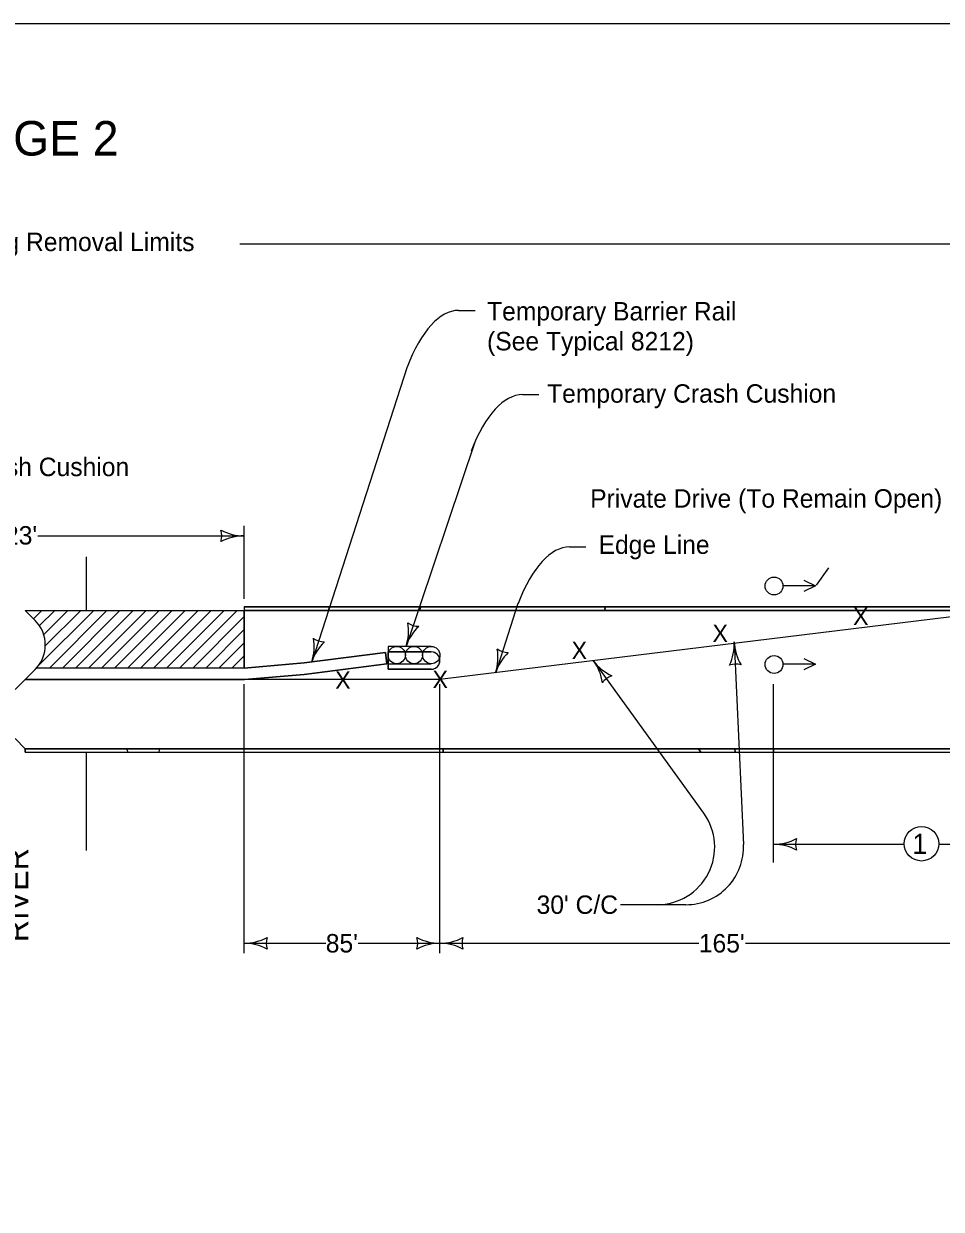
# Model space of a CAD drawing. Extents: x -2134934 to -2122394, y -2140205 to -2137036.
# Drawn here: x -2133366 to -2132569, y -2138065 to -2137036 of the extents above; entities that cross this region are included whole.
import ezdxf

# ---------------------------------------------------------------- set-up
doc = ezdxf.new("R2010")
doc.units = 0
for name, color, linetype in [('Barrier', 7, 'Continuous'), ('BridgeSuperStructureExisting', 7, 'Continuous'), ('Default', 7, 'Continuous'), ('dsnCellsNorthArrow', 7, 'Continuous'), ('DsnShtInsideBorder', 7, 'Continuous'), ('DsnShtPlotIdentification', 7, 'Continuous'), ('DsnShtPlotShape', 7, 'Continuous')]:
    doc.layers.add(name, color=color, linetype=linetype)

msp = doc.modelspace()

# ---------------------------------------------------------------- linework, layer by layer
at = {"layer": 'BridgeSuperStructureExisting'}
for p, q in [((-2133178, -2137227), (-2132514.4, -2137227)), ((-2132988.2, -2137284.8), (-2132973.9, -2137284.8)), ((-2133032.9, -2137333.9), (-2133115.7, -2137590)), ((-2132932.7, -2137357.9), (-2132918.5, -2137357.9)), ((-2132973.7, -2137398.2), (-2133033.8, -2137576.5)), ((-2133174.4, -2137535.2), (-2133174.4, -2137471.9)), ((-2133353.3, -2137480.5), (-2133174.4, -2137480.5)), ((-2133311.5, -2137498.8), (-2133311.5, -2137545.2)), ((-2132891.9, -2137490.1), (-2132877.7, -2137490.1)), ((-2132677.6, -2137523.2), (-2132666.8, -2137508.1)), ((-2132706.7, -2137523.7), (-2132678.8, -2137523.7)), ((-2132936.7, -2137539.2), (-2132956, -2137599.2)), ((-2133355.7, -2137553.9), (-2133364.4, -2137545.2)), ((-2133357.2, -2137552.4), (-2133350, -2137545.2)), ((-2133353.3, -2137593.7), (-2133304.8, -2137545.2)), ((-2133352, -2137558.4), (-2133338.7, -2137545.2)), ((-2133348.3, -2137566.1), (-2133327.4, -2137545.2)), ((-2133346.9, -2137576), (-2133316.1, -2137545.2)), ((-2133343.4, -2137595.2), (-2133293.4, -2137545.2)), ((-2133332.1, -2137595.2), (-2133282.1, -2137545.2)), ((-2133320.8, -2137595.2), (-2133270.8, -2137545.2)), ((-2133309.5, -2137595.2), (-2133259.5, -2137545.2)), ((-2133298.2, -2137595.2), (-2133248.2, -2137545.2)), ((-2133286.9, -2137595.2), (-2133236.9, -2137545.2)), ((-2133275.6, -2137595.2), (-2133225.6, -2137545.2)), ((-2133264.2, -2137595.2), (-2133214.2, -2137545.2)), ((-2133252.9, -2137595.2), (-2133202.9, -2137545.2)), ((-2133241.6, -2137595.2), (-2133191.6, -2137545.2)), ((-2133230.3, -2137595.2), (-2133180.3, -2137545.2)), ((-2133219, -2137595.2), (-2133174.4, -2137550.6)), ((-2133174.4, -2137595.2), (-2133174.4, -2137545.2)), ((-2131862, -2137545.2), (-2133174.4, -2137545.2)), ((-2133174.4, -2137545.2), (-2133174.4, -2137595.2)), ((-2132514.4, -2137545.2), (-2133004.4, -2137605.2)), ((-2133207.7, -2137595.2), (-2133174.4, -2137561.9)), ((-2133196.4, -2137595.2), (-2133174.4, -2137573.2)), ((-2133049.4, -2137576.5), (-2133049.4, -2137591.5)), ((-2133011.9, -2137576.5), (-2133049.4, -2137576.5)), ((-2133049.4, -2137596.2), (-2133049.4, -2137581.2)), ((-2133049.4, -2137581.2), (-2133011.9, -2137581.2)), ((-2132749, -2137572.6), (-2132740.9, -2137748.3)), ((-2133185.1, -2137595.2), (-2133174.4, -2137584.5)), ((-2133174.4, -2137595.2), (-2133122.2, -2137590.8)), ((-2133122.2, -2137590.8), (-2133174.3, -2137595.2)), ((-2133174.3, -2137595.2), (-2133122.2, -2137590.8)), ((-2133122.3, -2137600.8), (-2133050.4, -2137591.5)), ((-2133050.4, -2137591.5), (-2133122.3, -2137600.8)), ((-2133050.4, -2137591.5), (-2133122.3, -2137600.8)), ((-2133051.7, -2137581.6), (-2133122.2, -2137590.8)), ((-2133122.2, -2137590.8), (-2133051.7, -2137581.6)), ((-2133122.2, -2137590.8), (-2133051.7, -2137581.6)), ((-2133050.4, -2137591.5), (-2133051.7, -2137581.6)), ((-2133051.7, -2137581.6), (-2133050.4, -2137591.5)), ((-2133051.7, -2137581.6), (-2133050.4, -2137591.5)), ((-2133049.4, -2137591.5), (-2133011.9, -2137591.5)), ((-2132775.4, -2137721.3), (-2132871.2, -2137588.8)), ((-2132706.7, -2137591.7), (-2132678.8, -2137591.7)), ((-2133373.2, -2137613.9), (-2133355.7, -2137596.4)), ((-2133355.7, -2137596.4), (-2133364.4, -2137605.2)), ((-2133174.3, -2137595.2), (-2133354.4, -2137595.2)), ((-2133174.3, -2137595.2), (-2133354.4, -2137595.2)), ((-2133173.9, -2137605.2), (-2133122.3, -2137600.8)), ((-2133122.3, -2137600.8), (-2133173.9, -2137605.2)), ((-2133122.3, -2137600.8), (-2133173.9, -2137605.2)), ((-2133011.9, -2137596.2), (-2133049.4, -2137596.2)), ((-2133364.4, -2137605.2), (-2133173.9, -2137605.2)), ((-2133173.9, -2137605.2), (-2133364.4, -2137605.2)), ((-2133173.9, -2137605.2), (-2133364.4, -2137605.2)), ((-2133174.4, -2137842.8), (-2133174.4, -2137609.3)), ((-2133004.4, -2137605.2), (-2133173.9, -2137605.2)), ((-2133004.4, -2137842.8), (-2133004.4, -2137609.3)), ((-2132714.9, -2137764.1), (-2132714.9, -2137609.3)), ((-2133364.4, -2137665.2), (-2133373.2, -2137656.4)), ((-2133373.2, -2137656.4), (-2133364.4, -2137665.2)), ((-2133364.4, -2137665.2), (-2131862, -2137665.2)), ((-2133311.5, -2137668.2), (-2133311.5, -2137753.6)), ((-2132714.9, -2137748.2), (-2132601.4, -2137748.2)), ((-2132571.4, -2137748.2), (-2132514.9, -2137748.2)), ((-2132790.9, -2137800.6), (-2132847.6, -2137800.6)), ((-2133174.4, -2137834.1), (-2133103.5, -2137834.1)), ((-2133075.4, -2137834.1), (-2133004.4, -2137834.1)), ((-2133004.4, -2137834.1), (-2132779.7, -2137834.1)), ((-2132739.2, -2137834.1), (-2132514.4, -2137834.1))]:
    msp.add_line(p, q, dxfattribs=at)
for points in [[(-2132688.4, -2137518.9), (-2132678.4, -2137523.9), (-2132688.4, -2137528.9)], [(-2133364.4, -2137545.2), (-2133174.4, -2137545.2)], [(-2132688.4, -2137586.9), (-2132678.4, -2137591.9), (-2132688.4, -2137596.9)], [(-2133354.4, -2137595.2), (-2133354.5, -2137595.1)], [(-2133364.4, -2137605.2), (-2133364.4, -2137605.2), (-2133373.2, -2137613.9)]]:
    msp.add_lwpolyline(points, dxfattribs=at)
for centre, radius in [((-2132714.4, -2137524), 7.74), ((-2133041.9, -2137584), 7.5), ((-2133041.9, -2137584), 7.5), ((-2133026.9, -2137584), 7.5), ((-2133026.9, -2137584), 7.5), ((-2133011.9, -2137584), 7.5), ((-2133011.9, -2137584), 7.5), ((-2132714.4, -2137592.1), 7.74), ((-2132586.4, -2137747.7), 15)]:
    msp.add_circle(centre, radius, dxfattribs=at)
for centre, radius, start, end in [((-2133210.1, -2137480.5), 16.4, 342.2666, 17.7333), ((-2133174.4, -2137438), 42.5, 241.9275, 270), ((-2133174.4, -2137523), 42.5, 90, 118.0725), ((-2133376.9, -2137575.2), 30, 315, 45), ((-2133011.9, -2137588.7), 7.5, 269.9996, 90), ((-2133376.9, -2137575.2), 30, 315, 318.2713), ((-2132815.9, -2137750.6), 50, 270, 35.862), ((-2132714.9, -2137705.7), 42.5, 270, 298.0725), ((-2132679.3, -2137748.2), 16.4, 162.2666, 197.7334), ((-2132790.9, -2137750.6), 50, 270, 2.6154), ((-2132714.9, -2137790.7), 42.5, 61.9275, 90)]:
    msp.add_arc(centre, radius, start, end, dxfattribs=at)
for centre in [(-2132988.2, -2137497.7), (-2132932.7, -2137570.8), (-2132891.9, -2137703)]:
    msp.add_ellipse(centre, major_axis=(0, 212.9), ratio=0.328743, start_param=0, end_param=0.693162, dxfattribs=at)
at = {"layer": 'Default'}
msp.add_lwpolyline([(-2134934.4, -2137035.9), (-2131799.4, -2137035.9), (-2131799.4, -2139045.9), (-2134934.4, -2139045.9)], close=True, dxfattribs=at)
at = {"layer": 'DsnShtInsideBorder'}
for p, q in [((-2133011.9, -2137581.2), (-2133049.4, -2137581.2)), ((-2133049.4, -2137581.2), (-2133049.4, -2137596.2)), ((-2133049.4, -2137596.2), (-2133011.9, -2137596.2))]:
    msp.add_line(p, q, dxfattribs=at)
msp.add_arc((-2133011.9, -2137588.7), 7.5, 270.0024, 89.9972, dxfattribs=at)
at = {"layer": 'DsnShtPlotIdentification'}
for p, q in [((-2133174.4, -2137542.2), (-2133174.4, -2137545.2)), ((-2133174.4, -2137542.2), (-2133174.4, -2137545.2)), ((-2133100.2, -2137542.2), (-2133174.4, -2137542.2)), ((-2133174.4, -2137545.2), (-2133173.7, -2137545.2)), ((-2133173.7, -2137545.2), (-2133101.2, -2137545.2)), ((-2133100.2, -2137542.2), (-2133101.2, -2137545.2)), ((-2133101.2, -2137545.2), (-2133100.2, -2137542.2)), ((-2133101.2, -2137545.2), (-2133022.1, -2137545.2)), ((-2133021.1, -2137542.2), (-2133100.2, -2137542.2)), ((-2133021.1, -2137542.2), (-2133022.1, -2137545.2)), ((-2133022.1, -2137545.2), (-2133021.1, -2137542.2)), ((-2133022.1, -2137545.2), (-2132861.6, -2137545.2)), ((-2132860.7, -2137542.2), (-2133021.1, -2137542.2)), ((-2132860.7, -2137542.2), (-2132861.6, -2137545.2)), ((-2132861.6, -2137545.2), (-2132860.7, -2137542.2)), ((-2132861.6, -2137545.2), (-2132568.7, -2137545.2)), ((-2132547, -2137542.2), (-2132860.7, -2137542.2)), ((-2133364.4, -2137668.2), (-2133364.4, -2137665.2)), ((-2133364.4, -2137665.2), (-2131862, -2137665.2)), ((-2133364.4, -2137665.2), (-2131862, -2137665.2)), ((-2133276.3, -2137665.2), (-2133364.4, -2137665.2)), ((-2133364.4, -2137665.2), (-2133364.4, -2137668.2)), ((-2133364.4, -2137668.2), (-2131862, -2137668.2)), ((-2133364.4, -2137668.2), (-2133275.4, -2137668.2)), ((-2133247.5, -2137665.2), (-2133276.3, -2137665.2)), ((-2133275.4, -2137668.2), (-2133248.5, -2137668.2)), ((-2133248.5, -2137668.2), (-2133001.5, -2137668.2)), ((-2133001.5, -2137665.2), (-2133247.5, -2137665.2)), ((-2133001.5, -2137668.2), (-2133001.5, -2137665.2)), ((-2132780.1, -2137665.2), (-2133001.5, -2137665.2)), ((-2133001.5, -2137665.2), (-2133001.5, -2137668.2)), ((-2133001.5, -2137668.2), (-2132778, -2137668.2)), ((-2132778, -2137668.2), (-2132780.1, -2137665.2)), ((-2132780.1, -2137665.2), (-2132778, -2137668.2)), ((-2132748.3, -2137665.2), (-2132780.1, -2137665.2)), ((-2132778, -2137668.2), (-2132748.2, -2137668.2)), ((-2132748.2, -2137668.2), (-2132748.3, -2137665.2)), ((-2132714.9, -2137665.2), (-2132748.3, -2137665.2)), ((-2132748.3, -2137665.2), (-2132748.2, -2137668.2)), ((-2132748.2, -2137668.2), (-2132714.9, -2137668.2)), ((-2132714.9, -2137668.2), (-2132714.9, -2137665.2)), ((-2132441.1, -2137665.2), (-2132714.9, -2137665.2)), ((-2132714.9, -2137665.2), (-2132714.9, -2137668.2)), ((-2132714.9, -2137668.2), (-2132442.1, -2137668.2))]:
    msp.add_line(p, q, dxfattribs=at)
for points in [[(-2133174.4, -2137542.2), (-2131862, -2137542.2)], [(-2133174.4, -2137545.2), (-2131862, -2137545.2)], [(-2133173.7, -2137545.2), (-2131861.3, -2137545.2)]]:
    msp.add_lwpolyline(points, dxfattribs=at)
for start, end in [(191.3299, 203.618), (191.3299, 203.618), (336.382, 348.6701), (336.382, 348.6701)]:
    msp.add_arc((-2133261.9, -2137662.3), 14.7, start, end, dxfattribs=at)
at = {"layer": 'DsnShtPlotShape'}
for centre, radius, start, end in [((-2133074.2, -2137563.4), 42.5, 342.0849, 10.1574), ((-2132993.3, -2137589.6), 42.5, 134.0124, 162.0849), ((-2133022.8, -2137542.6), 16.4, 234.3516, 269.8183), ((-2133156.1, -2137576.9), 42.5, 342.0849, 10.1574), ((-2133104.7, -2137556.1), 16.4, 234.3516, 269.8183), ((-2133075.2, -2137603.1), 42.5, 134.0124, 162.0849), ((-2132996.5, -2137586.2), 42.5, 342.0849, 10.1574), ((-2132945.1, -2137565.3), 16.4, 234.3516, 269.8183), ((-2132791.4, -2137574.5), 42.5, 334.5429, 2.6154), ((-2132706.5, -2137570.6), 42.5, 182.6154, 210.6879), ((-2132915.6, -2137612.3), 42.5, 134.0124, 162.0849), ((-2132836.9, -2137563.7), 42.5, 216.299, 244.3715), ((-2132905.4, -2137614), 42.5, 8.2265, 36.299), ((-2132747.3, -2137608.2), 16.4, 74.8821, 110.3488), ((-2132850.1, -2137617.6), 16.4, 108.5657, 144.0324), ((-2133174.4, -2137791.6), 42.5, 270, 298.0725), ((-2133174.4, -2137876.6), 42.5, 61.9275, 90), ((-2133138.8, -2137834.1), 16.4, 162.2666, 197.7334), ((-2133040, -2137834.1), 16.4, 342.2666, 17.7333), ((-2133004.4, -2137791.6), 42.5, 241.9275, 270), ((-2133004.4, -2137876.6), 42.5, 90, 118.0725), ((-2133004.4, -2137791.6), 42.5, 270, 298.0725), ((-2133004.4, -2137876.6), 42.5, 61.9275, 90), ((-2132968.8, -2137834.1), 16.4, 162.2666, 197.7334)]:
    msp.add_arc(centre, radius, start, end, dxfattribs=at)

# ---------------------------------------------------------------- texts
at = {"layer": 'Barrier'}
msp.add_text('STAGE 2', height=30, dxfattribs=at).set_placement((-2133452.8, -2137150.4))
at = {"layer": 'BridgeSuperStructureExisting'}
for s, height, p in [('Pavement Marking Removal Limits', 16, (-2133548, -2137233.3)), ('Temporary Barrier Rail', 16, (-2132963.5, -2137293.5)), ('(See Typical 8212)', 16, (-2132963.5, -2137319.5)), ('Temporary Crash Cushion', 16, (-2132911.4, -2137364.9)), ('Temporary Crash Cushion', 16, (-2133525, -2137428.6)), ('Private Drive (To Remain Open)', 16, (-2132874, -2137456)), ("423'", 16, (-2133393.8, -2137488)), ('Edge Line', 16, (-2132866.7, -2137496.1)), ('X', 15, (-2133095.3, -2137613.2)), ('X', 15, (-2133010.8, -2137612.6)), ('1', 17.5, (-2132594.4, -2137756.5)), ("30' C/C", 16, (-2132920.5, -2137808.6)), ("85'", 16, (-2133103.5, -2137842.1)), ("165'", 16, (-2132779.7, -2137842.1))]:
    msp.add_text(s, height=height, dxfattribs=at).set_placement(p)
for p in [(-2132645.8, -2137557.8), (-2132767.8, -2137572.6), (-2132890.1, -2137587.4)]:
    msp.add_text('X', height=15, rotation=359.9705, dxfattribs=at).set_placement(p)
at = {"layer": 'dsnCellsNorthArrow'}
msp.add_text('RIVER', height=20, rotation=90, dxfattribs=at).set_placement((-2133361.7, -2137833.2))

doc.saveas('drawing.dxf')
